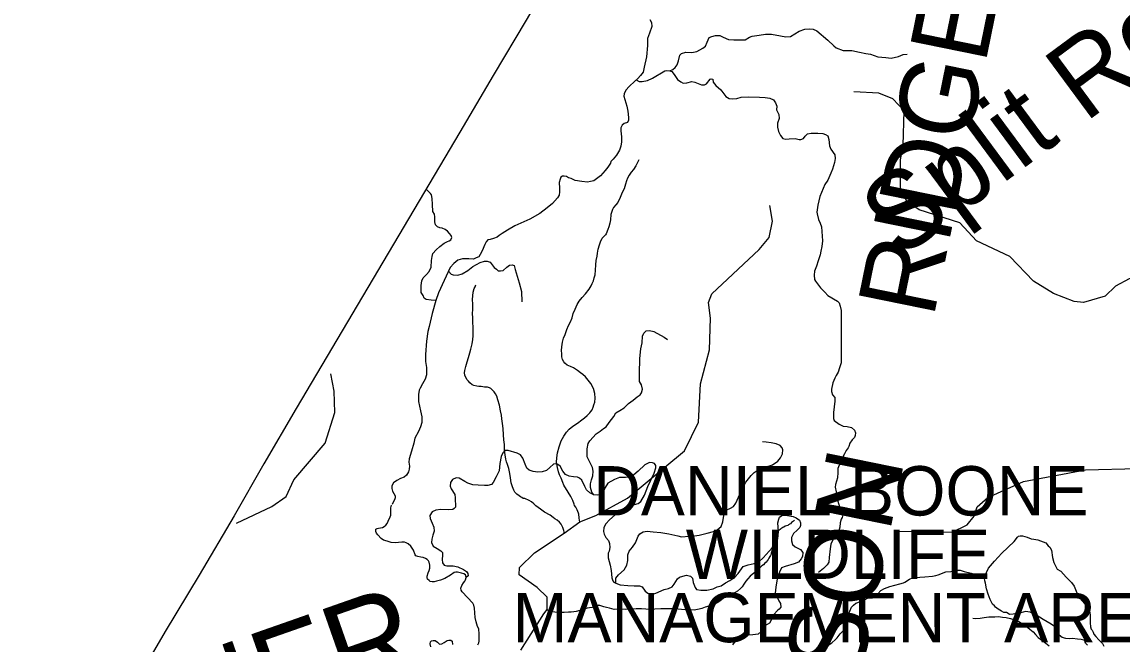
# Model space of a CAD drawing. Extents: x 1159738 to 1321356, y 736314 to 882035.
# Drawn here: x 1180449 to 1192923, y 838429 to 845489 of the extents above; entities that cross this region are included whole.
import ezdxf

# ---------------------------------------------------------------- set-up
doc = ezdxf.new("R2010")
doc.units = 0
for name, color, linetype in [('Exist Boundary Land Use Forest National US Forest Service Label', 7, 'Continuous'), ('Exist Boundary Political CountyLine', 7, 'Continuous'), ('Exist Geographical Mountain Summit Label', 7, 'Continuous'), ('Exist Hydrographic Creek Single Shore', 7, 'Continuous'), ('Exist Hydrographic Misc Water Feature', 7, 'Continuous'), ('Exist Road Non-System Type 51', 7, 'Continuous'), ('Exist Road State Agency Type 41 Label', 7, 'Continuous'), ('Exist Road State Agency Type 41 National Forest', 7, 'Continuous')]:
    doc.layers.add(name, color=color, linetype=linetype)

msp = doc.modelspace()

# ---------------------------------------------------------------- linework, layer by layer
at = {"layer": 'Exist Boundary Political CountyLine'}
msp.add_lwpolyline([(1191569, 854642), (1187998, 848563), (1186922, 846796), (1186165, 845509), (1185791, 844883), (1185414, 844237), (1183559, 841103), (1183190, 840473), (1182853, 839885), (1182456, 839211), (1182071, 838570), (1181698, 837930), (1180939, 836649), (1180581, 836034), (1180196, 835393)], dxfattribs=at)
at = {"layer": 'Exist Hydrographic Creek Single Shore'}
for points in [[(1194432, 842362), (1193599, 842418), (1193409, 842475), (1193137, 842598), (1193003, 842575), (1192851, 842489), (1192731, 842377), (1192487, 842306), (1192379, 842318), (1192148, 842408), (1191918, 842547), (1191651, 842828), (1191272, 843007), (1191086, 843210), (1190623, 843358), (1190483, 843452), (1190412, 843598), (1190413, 843923), (1190442, 844087), (1190453, 844480), (1190323, 844618), (1190166, 844680), (1189883, 844695)], [(1186105, 838360), (1186367, 838772), (1186403, 838822), (1186406, 838961), (1186292, 839072), (1186088, 839214), (1186090, 839296), (1186262, 839466), (1186597, 839689), (1186775, 839816), (1186957, 839889)]]:
    msp.add_lwpolyline(points, dxfattribs=at)
at = {"layer": 'Exist Hydrographic Misc Water Feature'}
for points in [[(1187443, 843926), (1187430, 843893), (1187409, 843855), (1187382, 843814), (1187357, 843786), (1187334, 843751), (1187315, 843718), (1187304, 843688), (1187291, 843648), (1187276, 843595), (1187255, 843553), (1187231, 843496), (1187204, 843439), (1187183, 843415), (1187156, 843382), (1187145, 843362), (1187139, 843340), (1187128, 843305), (1187122, 843243), (1187115, 843205), (1187104, 843165), (1187091, 843132), (1187072, 843084), (1187064, 843072)], [(1186957, 839889), (1187315, 840085), (1187963, 840621), (1188122, 840949), (1188143, 841382), (1188245, 841770), (1188255, 842128), (1188234, 842306), (1188270, 842404), (1188809, 842908), (1188921, 843044), (1188960, 843227), (1188931, 843405)], [(1186775, 839816), (1186772, 839832), (1186766, 839862), (1186764, 839903), (1186760, 839915), (1186752, 839933), (1186745, 839953), (1186737, 839967), (1186728, 839982), (1186716, 840002), (1186711, 840016), (1186694, 840057), (1186671, 840103), (1186641, 840152), (1186595, 840232), (1186582, 840264), (1186563, 840312), (1186546, 840351), (1186533, 840385), (1186520, 840432), (1186512, 840494), (1186513, 840542), (1186521, 840598), (1186539, 840669), (1186565, 840737), (1186593, 840790), (1186624, 840833), (1186653, 840868), (1186696, 840901), (1186747, 840936), (1186798, 840972), (1186829, 840997), (1186857, 841023), (1186888, 841052), (1186901, 841067), (1186915, 841087), (1186926, 841117), (1186935, 841143), (1186944, 841176), (1186949, 841218), (1186946, 841272), (1186930, 841331), (1186898, 841386), (1186869, 841423), (1186838, 841462), (1186810, 841488), (1186783, 841509), (1186750, 841534), (1186703, 841563), (1186669, 841580), (1186631, 841595), (1186604, 841616), (1186592, 841633), (1186579, 841659), (1186572, 841687), (1186571, 841723), (1186566, 841761), (1186571, 841803), (1186577, 841857), (1186588, 841901), (1186607, 841942), (1186629, 841998), (1186648, 842045), (1186669, 842087), (1186689, 842132), (1186700, 842180), (1186723, 842231), (1186743, 842283), (1186766, 842320), (1186803, 842361), (1186838, 842402), (1186882, 842457), (1186905, 842494), (1186916, 842522), (1186929, 842552), (1186938, 842586), (1186947, 842621), (1186952, 842673), (1186956, 842733), (1186961, 842783), (1186971, 842831), (1186975, 842865), (1186983, 842911), (1186996, 842958), (1187009, 842992), (1187028, 843035), (1187064, 843072)], [(1186597, 839683), (1186597, 839689), (1186596, 839703), (1186594, 839717), (1186591, 839729), (1186581, 839750), (1186574, 839766), (1186562, 839788), (1186543, 839811), (1186517, 839835), (1186492, 839852), (1186472, 839865), (1186437, 839890), (1186374, 839926), (1186329, 839961), (1186276, 839998), (1186253, 840021), (1186225, 840044), (1186201, 840059), (1186152, 840080), (1186134, 840082), (1186118, 840091), (1186101, 840099), (1186085, 840110), (1186059, 840131), (1186038, 840151), (1186027, 840176), (1186012, 840212), (1185997, 840260), (1185987, 840315), (1185980, 840365), (1185968, 840421), (1185953, 840468), (1185944, 840496), (1185935, 840528), (1185928, 840577), (1185920, 840635), (1185919, 840693), (1185913, 840747), (1185910, 840803), (1185904, 840874), (1185898, 840934), (1185892, 840984), (1185885, 841026), (1185876, 841076), (1185864, 841139), (1185846, 841201), (1185833, 841242), (1185819, 841270), (1185804, 841293), (1185785, 841311), (1185765, 841328), (1185749, 841336), (1185726, 841343), (1185694, 841346), (1185656, 841351), (1185628, 841352), (1185606, 841354), (1185572, 841365), (1185554, 841372), (1185529, 841393), (1185511, 841411), (1185498, 841429), (1185481, 841454), (1185471, 841480), (1185468, 841506), (1185469, 841532), (1185482, 841580), (1185498, 841632), (1185513, 841683), (1185529, 841733), (1185540, 841775), (1185554, 841838), (1185561, 841884), (1185564, 841928), (1185566, 841982), (1185565, 842030), (1185562, 842074), (1185560, 842134), (1185559, 842178), (1185561, 842230), (1185560, 842286), (1185558, 842338), (1185561, 842382), (1185566, 842424), (1185577, 842464), (1185586, 842484), (1185596, 842507)], [(1190399, 839712), (1190999, 839697), (1191168, 839782), (1191246, 839879), (1191282, 839986), (1191402, 840092), (1191807, 840275), (1192511, 840405), (1193103, 840423), (1193339, 840500), (1193584, 840626), (1193936, 840990), (1194129, 841344), (1194230, 841693), (1194327, 841888), (1194413, 841995), (1194432, 842362)], [(1182880, 839801), (1183283, 839992), (1183444, 840104), (1183533, 840292), (1183887, 840709), (1183997, 841058), (1183987, 841298), (1183951, 841497)], [(1189210, 839832), (1189187, 839816), (1189175, 839807), (1189164, 839795), (1189154, 839789), (1189150, 839785), (1189140, 839781), (1189132, 839776), (1189118, 839772), (1189102, 839766), (1189087, 839757), (1189077, 839753), (1189065, 839743), (1189053, 839736), (1189045, 839730), (1189036, 839722), (1189026, 839715), (1189020, 839705), (1189012, 839693), (1189005, 839683), (1188999, 839671), (1188993, 839659), (1188986, 839640), (1188980, 839622), (1188975, 839602), (1188971, 839584), (1188966, 839564), (1188961, 839536), (1188957, 839508), (1188948, 839472), (1188945, 839461), (1188943, 839451), (1188937, 839435), (1188930, 839423), (1188920, 839405), (1188911, 839389), (1188899, 839372), (1188889, 839360), (1188874, 839346), (1188858, 839329), (1188839, 839315), (1188827, 839304), (1188807, 839288), (1188761, 839245), (1188747, 839234), (1188706, 839201), (1188681, 839169), (1188657, 839144), (1188636, 839109), (1188615, 839079), (1188596, 839058), (1188561, 839031), (1188537, 839013), (1188521, 839006), (1188476, 838989), (1188438, 838974), (1188401, 838947), (1188362, 838914), (1188340, 838901), (1188303, 838883), (1188239, 838859), (1188198, 838846), (1188158, 838833), (1188128, 838824), (1188071, 838814), (1187995, 838816), (1187929, 838820), (1187851, 838830), (1187801, 838829), (1187693, 838828), (1187627, 838824), (1187579, 838821), (1187523, 838825), (1187475, 838828), (1187412, 838830), (1187352, 838826), (1187290, 838823), (1187220, 838825), (1187163, 838823), (1187112, 838836), (1187076, 838843), (1187048, 838850), (1187000, 838865), (1186992, 838868), (1186984, 838870), (1186978, 838866), (1186966, 838858), (1186946, 838853)], [(1186403, 838822), (1186420, 838811), (1186448, 838803), (1186492, 838795), (1186536, 838792), (1186596, 838792), (1186646, 838793), (1186678, 838796), (1186736, 838801), (1186777, 838813), (1186862, 838841), (1186884, 838842), (1186946, 838853)], [(1191231, 838722), (1191259, 838719), (1191315, 838722), (1191361, 838731), (1191414, 838737), (1191445, 838738), (1191480, 838739), (1191522, 838740), (1191567, 838735), (1191611, 838730), (1191659, 838719), (1191691, 838708), (1191727, 838695), (1191760, 838680), (1191807, 838651), (1191837, 838632), (1191878, 838599), (1191915, 838566), (1191942, 838537), (1191974, 838504), (1192013, 838475), (1192058, 838440), (1192099, 838407)]]:
    msp.add_lwpolyline(points, dxfattribs=at)
at = {"layer": 'Exist Road Non-System Type 51'}
for points in [[(1187794, 844936), (1187828, 844949), (1187856, 844971), (1187878, 845002), (1187892, 845049), (1187909, 845111), (1187928, 845130), (1187978, 845146), (1188045, 845144), (1188102, 845154), (1188168, 845191), (1188200, 845216), (1188219, 845260), (1188242, 845311), (1188273, 845325), (1188314, 845337), (1188362, 845334), (1188399, 845315), (1188461, 845292), (1188523, 845287), (1188600, 845285), (1188650, 845287), (1188699, 845315), (1188730, 845329), (1188810, 845340), (1188882, 845352), (1188948, 845349), (1189050, 845332), (1189112, 845321), (1189162, 845325), (1189213, 845354), (1189262, 845385), (1189325, 845406), (1189379, 845411), (1189422, 845406), (1189462, 845387), (1189589, 845283), (1189656, 845218), (1189680, 845196), (1189761, 845166), (1189859, 845165), (1189947, 845147), (1190019, 845130), (1190071, 845123), (1190154, 845092), (1190245, 845087), (1190307, 845080), (1190390, 845096), (1190442, 845121), (1190488, 845125)], [(1187415, 844831), (1187449, 844815), (1187480, 844814), (1187542, 844826), (1187599, 844852), (1187737, 844934), (1187756, 844938), (1187794, 844936), (1187820, 844927), (1187844, 844893), (1187884, 844838), (1187920, 844810), (1187947, 844796), (1187989, 844798), (1188044, 844812), (1188078, 844807), (1188153, 844774), (1188190, 844774), (1188213, 844786), (1188254, 844841), (1188265, 844845), (1188282, 844839), (1188287, 844807), (1188318, 844767), (1188373, 844719), (1188432, 844643), (1188468, 844620), (1188504, 844615), (1188556, 844620), (1188604, 844634), (1188683, 844638), (1188811, 844636), (1188875, 844631), (1188930, 844624), (1188970, 844605), (1188992, 844570), (1189010, 844534), (1189006, 844491), (1189030, 844438), (1189036, 844393), (1189017, 844341), (1189015, 844294), (1189029, 844247), (1189051, 844199), (1189077, 844168), (1189111, 844159), (1189148, 844161), (1189215, 844168), (1189261, 844157), (1189282, 844156), (1189310, 844168), (1189330, 844192), (1189356, 844218), (1189398, 844228), (1189472, 844228), (1189529, 844223), (1189561, 844211), (1189589, 844195), (1189598, 844157), (1189608, 844083), (1189622, 844047), (1189665, 843983), (1189670, 843940), (1189661, 843894), (1189641, 843818), (1189623, 843773), (1189589, 843693), (1189554, 843643), (1189515, 843555), (1189498, 843510), (1189473, 843411), (1189463, 843332), (1189468, 843310), (1189480, 843249), (1189501, 843206), (1189514, 843166), (1189521, 843112), (1189525, 843004), (1189518, 842940), (1189506, 842888), (1189501, 842845), (1189478, 842780), (1189458, 842717), (1189437, 842662), (1189432, 842617), (1189435, 842567), (1189447, 842549), (1189504, 842473), (1189554, 842421), (1189589, 842385), (1189697, 842321), (1189716, 842302), (1189726, 842263), (1189738, 842216), (1189740, 842057), (1189737, 842000), (1189740, 841831), (1189737, 841619), (1189718, 841564), (1189706, 841515), (1189680, 841476)], [(1185140, 842328), (1185090, 842331), (1185031, 842340), (1185009, 842356), (1184998, 842383), (1184976, 842418), (1184974, 842448), (1184977, 842500), (1184984, 842551), (1184999, 842584), (1185037, 842625), (1185067, 842657), (1185090, 842706), (1185094, 842783), (1185099, 842827), (1185108, 842861), (1185145, 842904), (1185188, 842942), (1185235, 842978), (1185273, 842999), (1185293, 843007), (1185311, 843018), (1185322, 843042), (1185317, 843066), (1185298, 843088), (1185275, 843115), (1185249, 843132), (1185213, 843148), (1185186, 843154), (1185161, 843164), (1185137, 843187), (1185129, 843222), (1185129, 843276), (1185126, 843306), (1185107, 843339), (1185105, 843416), (1185101, 843486), (1185093, 843527), (1185082, 843544), (1185031, 843590)], [(1185287, 842660), (1185314, 842627), (1185337, 842619), (1185392, 842614), (1185440, 842632), (1185506, 842670), (1185561, 842714), (1185645, 842760), (1185692, 842776), (1185723, 842776), (1185759, 842762), (1185804, 842703), (1185828, 842683), (1185850, 842665), (1185876, 842665), (1185905, 842670), (1185947, 842705), (1185976, 842729), (1186007, 842733), (1186030, 842726), (1186043, 842681), (1186088, 842527), (1186112, 842431), (1186116, 842313)], [(1186935, 840121), (1186912, 840152), (1186897, 840205), (1186897, 840248), (1186906, 840291), (1186923, 840338), (1186926, 840390), (1186919, 840433), (1186887, 840492), (1186859, 840554), (1186859, 840643), (1186869, 840704), (1186887, 840737), (1186961, 840814), (1187004, 840845), (1187045, 840876), (1187073, 840894), (1187107, 840943), (1187159, 841012), (1187183, 841055), (1187228, 841081), (1187278, 841110), (1187326, 841160), (1187380, 841198), (1187426, 841236), (1187459, 841258), (1187476, 841279), (1187485, 841320), (1187476, 841370), (1187452, 841408), (1187453, 841499), (1187457, 841669), (1187465, 841781), (1187481, 841847), (1187486, 841925), (1187502, 841959), (1187527, 841985), (1187564, 841988), (1187614, 841975), (1187733, 841911), (1187769, 841885)], [(1189680, 841476), (1189666, 841446), (1189644, 841392), (1189630, 841323), (1189630, 841296), (1189640, 841258), (1189666, 841228), (1189666, 841185), (1189652, 841058), (1189651, 840990), (1189659, 840966), (1189714, 840923), (1189761, 840902), (1189807, 840897), (1189857, 840885), (1189888, 840856), (1189902, 840826), (1189899, 840795), (1189888, 840774), (1189864, 840748), (1189837, 840710), (1189825, 840672), (1189816, 840657), (1189795, 840627), (1189778, 840586), (1189752, 840546), (1189726, 840484), (1189702, 840420), (1189702, 840376), (1189697, 840315), (1189676, 840241), (1189671, 840210), (1189683, 840155), (1189687, 840104), (1189690, 840080), (1189702, 840049), (1189718, 839987)], [(1188517, 839991), (1188545, 840028), (1188589, 840129), (1188658, 840266), (1188717, 840343), (1188751, 840376), (1188807, 840412), (1188889, 840440), (1188958, 840464), (1189020, 840504), (1189050, 840543), (1189072, 840587), (1189077, 840635), (1189070, 840657), (1189048, 840681), (1189000, 840700), (1188943, 840712), (1188889, 840719), (1188845, 840725)], [(1187352, 839993), (1187395, 840011), (1187435, 840024), (1187467, 840048), (1187507, 840119), (1187547, 840218), (1187619, 840369), (1187638, 840430), (1187636, 840456), (1187622, 840480), (1187598, 840487), (1187564, 840490), (1187512, 840462), (1187438, 840393), (1187388, 840350), (1187345, 840323), (1187293, 840319), (1187226, 840318), (1187169, 840295), (1187093, 840255), (1187061, 840207), (1187030, 840142), (1187009, 840124), (1186976, 840117), (1186935, 840121), (1186888, 840147), (1186850, 840181), (1186830, 840218), (1186797, 840288), (1186771, 840312), (1186749, 840324), (1186702, 840328), (1186654, 840333), (1186614, 840354), (1186581, 840392), (1186550, 840449), (1186524, 840468), (1186502, 840473), (1186475, 840469), (1186435, 840433), (1186397, 840400), (1186347, 840383), (1186300, 840380), (1186244, 840388), (1186200, 840402), (1186173, 840426), (1186156, 840469), (1186130, 840537), (1186103, 840577), (1186065, 840596), (1185963, 840624), (1185927, 840624), (1185901, 840601), (1185881, 840558), (1185869, 840479), (1185860, 840396), (1185826, 840327), (1185793, 840262), (1185772, 840239), (1185732, 840229), (1185695, 840227), (1185622, 840232), (1185560, 840236), (1185505, 840255), (1185470, 840274), (1185408, 840313), (1185374, 840317), (1185329, 840298), (1185307, 840262), (1185305, 840222), (1185317, 840191), (1185359, 840126), (1185361, 840088), (1185364, 839983)], [(1185364, 839983), (1185351, 839966), (1185333, 839955), (1185287, 839951), (1185199, 839956), (1185143, 839949), (1185101, 839928), (1185074, 839887), (1185078, 839854), (1185101, 839801), (1185120, 839756), (1185122, 839710), (1185108, 839666), (1185095, 839621), (1185091, 839581), (1185110, 839539), (1185155, 839514), (1185197, 839487), (1185216, 839469), (1185218, 839439), (1185214, 839390), (1185218, 839352), (1185235, 839325), (1185268, 839315), (1185337, 839315), (1185391, 839306), (1185457, 839277), (1185489, 839252), (1185505, 839231), (1185507, 839204), (1185485, 839186)], [(1187352, 839993), (1187288, 839963), (1187227, 839930), (1187175, 839894), (1187111, 839840), (1187071, 839794), (1187048, 839751), (1187042, 839707), (1187050, 839676), (1187069, 839638), (1187100, 839603), (1187111, 839572), (1187115, 839524), (1187107, 839484), (1187098, 839461), (1187098, 839407), (1187117, 839326), (1187132, 839264), (1187138, 839182), (1187150, 839148), (1187159, 839132), (1187184, 839119)], [(1187184, 839119), (1187184, 839175), (1187215, 839213), (1187278, 839271), (1187307, 839323), (1187321, 839377), (1187319, 839440), (1187334, 839483), (1187371, 839529), (1187405, 839579), (1187438, 839654), (1187455, 839681), (1187492, 839702), (1187538, 839712), (1187607, 839704), (1187694, 839696), (1187786, 839680), (1187888, 839657), (1187926, 839646), (1188013, 839652), (1188075, 839659), (1188130, 839663), (1188217, 839688), (1188292, 839707), (1188332, 839727), (1188379, 839763), (1188398, 839815), (1188407, 839887), (1188415, 839923), (1188436, 839949), (1188482, 839970), (1188517, 839991)], [(1189718, 839987), (1189744, 839943), (1189759, 839896), (1189751, 839866), (1189737, 839846), (1189726, 839806), (1189722, 839756), (1189710, 839699), (1189680, 839654), (1189645, 839613), (1189623, 839561), (1189614, 839511), (1189604, 839413), (1189600, 839358), (1189579, 839328), (1189538, 839285), (1189482, 839240)], [(1187184, 839119), (1187232, 839103), (1187321, 839095), (1187392, 839088), (1187450, 839088), (1187480, 839080), (1187517, 839028), (1187546, 839007), (1187578, 838995), (1187600, 838995), (1187638, 839007), (1187730, 839049), (1187782, 839059), (1187821, 839078), (1187846, 839109), (1187881, 839170), (1187906, 839190), (1187942, 839201), (1187986, 839209), (1188029, 839199), (1188052, 839178), (1188059, 839128), (1188083, 839072), (1188098, 839049), (1188146, 839041), (1188215, 839040), (1188286, 839055), (1188333, 839078), (1188379, 839088), (1188426, 839122), (1188476, 839151), (1188533, 839190), (1188572, 839230), (1188626, 839309), (1188685, 839328), (1188751, 839344), (1188805, 839363), (1188855, 839407), (1188955, 839521), (1188999, 839581), (1189020, 839625), (1189026, 839706), (1189022, 839806), (1189030, 839846), (1189041, 839868), (1189066, 839887), (1189107, 839891), (1189193, 839877), (1189228, 839862), (1189266, 839835), (1189278, 839804), (1189278, 839775), (1189268, 839752), (1189241, 839721), (1189199, 839683), (1189176, 839638), (1189174, 839600), (1189186, 839560), (1189216, 839534), (1189278, 839504), (1189303, 839467), (1189301, 839423), (1189286, 839398), (1189255, 839359), (1189205, 839338), (1189105, 839311), (1189062, 839294), (1189041, 839246), (1189012, 839171), (1188997, 839074), (1188991, 839005), (1189030, 838920), (1189049, 838890), (1189055, 838849), (1189037, 838824), (1189018, 838811), (1188976, 838764), (1188951, 838714), (1188924, 838667), (1188874, 838635), (1188832, 838573), (1188797, 838540), (1188737, 838535), (1188662, 838529), (1188599, 838506), (1188537, 838463), (1188505, 838421)], [(1192532, 838417), (1192510, 838440), (1192501, 838467), (1192491, 838475), (1192462, 838481), (1192418, 838486), (1192361, 838491), (1192323, 838488), (1192287, 838491), (1192245, 838503), (1192210, 838529), (1192186, 838551), (1192174, 838573), (1192156, 838628), (1192120, 838654), (1192029, 838708), (1191947, 838761), (1191880, 838790), (1191828, 838799), (1191777, 838783), (1191744, 838778), (1191689, 838770), (1191648, 838764), (1191634, 838775), (1191612, 838786), (1191585, 838789), (1191558, 838802), (1191520, 838824), (1191490, 838846), (1191478, 838861), (1191454, 838882), (1191429, 838934), (1191407, 838994), (1191388, 839057), (1191377, 839120), (1191369, 839148), (1191365, 839176), (1191388, 839242), (1191410, 839291), (1191478, 839371), (1191561, 839461), (1191700, 839592), (1191740, 839641), (1191751, 839654), (1191770, 839657), (1191795, 839657), (1191849, 839641), (1191895, 839622), (1191924, 839618), (1191968, 839613), (1192028, 839591), (1192058, 839577), (1192086, 839544), (1192104, 839530), (1192123, 839493), (1192135, 839413), (1192151, 839355), (1192175, 839300), (1192189, 839279), (1192228, 839257), (1192289, 839188), (1192350, 839126), (1192381, 839085), (1192411, 839012), (1192444, 838948), (1192499, 838890), (1192536, 838836), (1192558, 838790), (1192564, 838753), (1192562, 838668), (1192566, 838624), (1192575, 838598), (1192586, 838588), (1192595, 838565), (1192605, 838540), (1192625, 838513), (1192661, 838478), (1192702, 838434), (1192718, 838404)], [(1189587, 838411), (1189633, 838441), (1189676, 838480), (1189694, 838498), (1189729, 838546), (1189787, 838605), (1189796, 838626), (1189800, 838662), (1189803, 838712), (1189818, 838761), (1189836, 838802), (1189855, 838846), (1189878, 838871), (1189906, 838893), (1189958, 838912), (1190004, 838930), (1190046, 838952), (1190089, 838955), (1190111, 838971), (1190153, 838999), (1190190, 839037), (1190229, 839059), (1190290, 839081), (1190404, 839114), (1190444, 839125), (1190461, 839130), (1190514, 839165), (1190549, 839179), (1190577, 839185), (1190631, 839187), (1190686, 839192), (1190776, 839201), (1190813, 839207), (1190840, 839214), (1190927, 839248), (1190983, 839253), (1191012, 839256), (1191057, 839267), (1191087, 839266), (1191134, 839253), (1191211, 839234), (1191276, 839215), (1191321, 839209), (1191365, 839176)]]:
    msp.add_lwpolyline(points, dxfattribs=at)
at = {"layer": 'Exist Road State Agency Type 41 National Forest'}
msp.add_line((1185478, 839158), (1185485, 839186), dxfattribs=at)
for points in [[(1187570, 845518), (1187589, 845482), (1187592, 845438), (1187565, 845361), (1187541, 845301), (1187541, 845222), (1187530, 845093), (1187505, 844976), (1187493, 844918), (1187464, 844882), (1187432, 844848), (1187397, 844819), (1187333, 844758), (1187295, 844717), (1187279, 844675), (1187275, 844648), (1187307, 844532), (1187319, 844477), (1187328, 844404), (1187326, 844373), (1187314, 844349), (1187279, 844335), (1187256, 844318), (1187241, 844286), (1187240, 844255), (1187246, 844187), (1187249, 844128), (1187240, 844079), (1187223, 844035), (1187192, 843977), (1187153, 843931), (1187128, 843906), (1187121, 843885), (1187094, 843842), (1187061, 843805), (1187008, 843744), (1186935, 843688), (1186897, 843677), (1186860, 843671), (1186798, 843677), (1186722, 843691), (1186678, 843712), (1186646, 843720), (1186624, 843736), (1186597, 843740), (1186580, 843739), (1186561, 843728), (1186551, 843704), (1186542, 843666), (1186545, 843604)], [(1186545, 843604), (1186543, 843563), (1186539, 843525), (1186520, 843493), (1186463, 843429), (1186406, 843379), (1186320, 843316), (1186207, 843250), (1186039, 843174), (1185955, 843126), (1185893, 843090), (1185860, 843065), (1185838, 843047), (1185797, 843033), (1185759, 843022), (1185731, 843015), (1185711, 842994), (1185696, 842963), (1185668, 842892), (1185643, 842849), (1185628, 842824), (1185601, 842812), (1185570, 842798), (1185516, 842800), (1185443, 842800), (1185393, 842787), (1185347, 842748), (1185306, 842703), (1185236, 842555), (1185173, 842414), (1185140, 842328), (1185099, 842182), (1185067, 842033), (1185051, 841975), (1185036, 841868), (1185026, 841717), (1185023, 841635), (1185036, 841569), (1185036, 841529), (1185036, 841486), (1185021, 841437), (1184991, 841382), (1184964, 841334), (1184954, 841309), (1184946, 841260), (1184947, 841182), (1184969, 841076), (1184982, 841008), (1184982, 840942), (1184968, 840894), (1184944, 840842), (1184905, 840767), (1184892, 840708), (1184867, 840617), (1184840, 840531), (1184837, 840492), (1184843, 840447), (1184840, 840412), (1184830, 840384), (1184808, 840344), (1184783, 840322), (1184740, 840308), (1184701, 840286), (1184663, 840260), (1184644, 840226), (1184641, 840194), (1184652, 840164), (1184682, 840113), (1184682, 840088), (1184674, 840064), (1184656, 840040), (1184646, 840011)], [(1185485, 839186), (1185483, 839202), (1185477, 839214), (1185461, 839227), (1185434, 839235), (1185388, 839243), (1185370, 839244), (1185350, 839240), (1185309, 839211), (1185245, 839174), (1185195, 839155), (1185148, 839142), (1185124, 839137), (1185100, 839136), (1185079, 839139), (1185065, 839150), (1185048, 839167), (1185045, 839181), (1185044, 839201), (1185055, 839237), (1185066, 839264), (1185073, 839289), (1185072, 839326), (1185065, 839358), (1185057, 839373), (1185045, 839389), (1185024, 839399), (1184997, 839411), (1184971, 839416), (1184938, 839422), (1184916, 839431), (1184908, 839442), (1184887, 839495), (1184860, 839539), (1184828, 839568), (1184806, 839578), (1184786, 839584), (1184758, 839584), (1184717, 839581), (1184679, 839579), (1184637, 839582), (1184588, 839595), (1184549, 839609), (1184521, 839628), (1184484, 839669), (1184468, 839688), (1184463, 839705), (1184460, 839722), (1184462, 839732), (1184477, 839742), (1184493, 839745), (1184516, 839748), (1184538, 839753), (1184556, 839762), (1184575, 839779), (1184590, 839796), (1184603, 839824), (1184622, 839873), (1184632, 839890), (1184633, 839911), (1184633, 839941), (1184631, 839975), (1184639, 840004)], [(1185617, 838420), (1185628, 838441), (1185633, 838461), (1185635, 838541), (1185630, 838602), (1185616, 838627), (1185599, 838681), (1185588, 838731), (1185583, 838782), (1185581, 838836), (1185574, 838872), (1185563, 838892), (1185499, 838959), (1185439, 839021), (1185428, 839041), (1185426, 839064), (1185436, 839094), (1185454, 839122), (1185471, 839144), (1185478, 839158)], [(1185086, 838396), (1185079, 838430), (1185080, 838453), (1185091, 838465), (1185113, 838471), (1185135, 838470), (1185160, 838449), (1185184, 838429), (1185210, 838431), (1185238, 838446), (1185270, 838468), (1185289, 838475), (1185310, 838475), (1185328, 838463), (1185331, 838425)]]:
    msp.add_lwpolyline(points, dxfattribs=at)

# ---------------------------------------------------------------- texts
at = {"layer": 'Exist Boundary Land Use Forest National US Forest Service Label'}
for s, p in [('DANIEL BOONE', (1186926, 839888)), ('WILDLIFE', (1187976, 839169)), ('MANAGEMENT AREA', (1186011, 838450))]:
    msp.add_text(s, height=560, dxfattribs=at).set_placement(p)
at = {"layer": 'Exist Geographical Mountain Summit Label'}
for s, rotation, p in [('Split Rock Ridge', 36.4426, (1190397, 842785)), ('WILSON     RIDGE', 78.4852, (1189531, 835965))]:
    msp.add_text(s, height=880, rotation=rotation, dxfattribs=at).set_placement(p)
at = {"layer": 'Exist Road State Agency Type 41 Label'}
msp.add_text('NFR', height=1049.9, rotation=19.3244, dxfattribs=at).set_placement((1182332, 837176))

doc.saveas('drawing.dxf')
